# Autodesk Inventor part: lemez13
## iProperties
Created: 2015-01
Part Number: lemez13
Document SubType Name: Sheet Metal
Designer: Tulajdonos
Author: Tulajdonos
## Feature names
1. Lemez1
2. Lemez2
3. Hajlítás1
4. Lemez3
5. Hajlítás2
6. TerítékKihúzás1
7. Kivágás1
8. Kivágás2
